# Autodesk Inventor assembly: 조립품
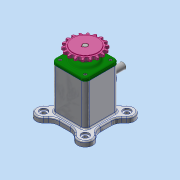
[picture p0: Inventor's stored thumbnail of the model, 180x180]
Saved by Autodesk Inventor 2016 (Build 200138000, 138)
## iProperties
Created: 2019-11
Part Number: 조립품
Material: 일반
Document SubType Name: Assembly
Designer: user
Author: user
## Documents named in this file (11)
- C:\Users\user\Desktop\491109V1001\조립품.iam
- C:\Users\user\Desktop\491109V1001\베어링 6203.ipt
- C:\Users\user\Desktop\491109V1001\본체.ipt
- C:\Users\user\Desktop\491109V1001\볼트 M4.ipt
- C:\Users\user\Desktop\491109V1001\부시.ipt
- C:\Users\user\Desktop\491109V1001\스프로킷.ipt
- C:\Users\user\Desktop\491109V1001\슬라이더.ipt
- C:\Users\user\Desktop\491109V1001\오일 실.ipt
- C:\Users\user\Desktop\491109V1001\커버.ipt
- C:\Users\user\Desktop\491109V1001\키 4 x 4 x 14.ipt
- C:\Users\user\Desktop\491109V1001\편심축.ipt
